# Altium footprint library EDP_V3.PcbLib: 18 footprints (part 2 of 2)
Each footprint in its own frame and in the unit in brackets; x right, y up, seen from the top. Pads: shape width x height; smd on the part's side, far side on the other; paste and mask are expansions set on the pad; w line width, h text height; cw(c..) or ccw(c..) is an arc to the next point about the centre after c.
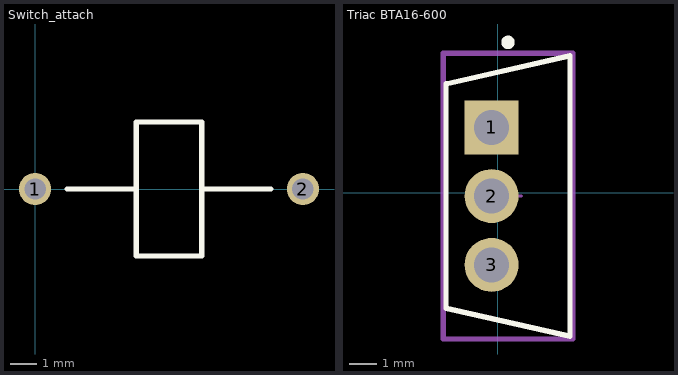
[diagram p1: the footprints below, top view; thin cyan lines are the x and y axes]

## Switch_attach [mm]
pads (2):
  round 1.2 hole 0.8: 1(0,0) 2(10,0)
Top Overlay:
  lines w0.2: 1.2,0 3.775,0 ; 6.225,0 8.8,0 ; 3.775,0 3.775,-2.5 6.225,-2.5 6.225,2.5 3.775,2.5 3.775,0

## Triac BTA16-600 [mm]
pads (3):
  rect 2x2 hole 1.3 paste-2539.97 mask+0: 1(-0.226,2.423)
  round 2 hole 1.3 paste-2539.97 mask+0: 2(-0.226,-0.127) 3(-0.226,-2.677)
Top Overlay:
  circle w0.25: c0.381,5.573 r0.125
  lines w0.2: 2.681,-5.327 -1.919,-4.287 -1.919,4.033 2.681,5.073 ; 2.681,-5.277 2.681,5.023
Board:
  lines w0.2: -2.019,-5.427 -2.019,5.173 2.781,5.173 2.781,-5.427 -2.019,-5.427
Top Assembly:
  lines w0.2: -2.019,-5.427 -2.019,5.173 2.781,5.173 2.781,-5.427 -2.019,-5.427
  text ".Designator" at 0.381,0.061 h1
Top Component Center:
  lines w0.1: -0.119,-0.127 0.881,-0.127 ; 0.381,-0.627 0.381,0.373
